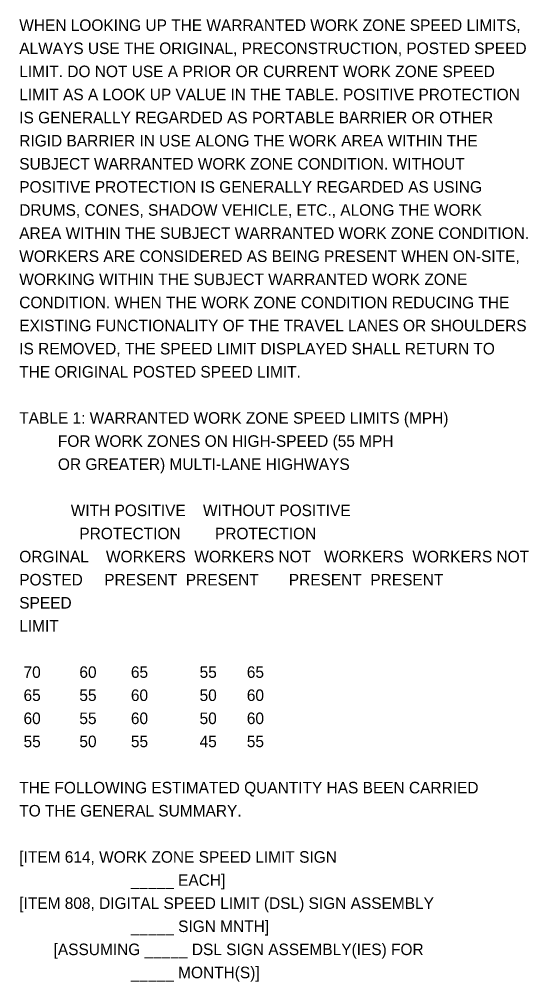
# Model space of a CAD drawing. Extents: x -9 to 65.1, y -15.6 to 23.2.
# Drawn here: x 39.08 to 45.25, y -8.1 to 3.56 of the extents above; entities that cross this region are included whole.
import ezdxf

# ---------------------------------------------------------------- set-up
doc = ezdxf.new("R2010")
doc.units = 0
doc.layers.add('SH_Text', color=7, linetype='Continuous')

msp = doc.modelspace()

# ---------------------------------------------------------------- texts
at = {"layer": 'SH_Text'}
for s, p in [('WHEN LOOKING UP THE WARRANTED WORK ZONE SPEED LIMITS,', (39.076, 3.42)), ('ALWAYS USE THE ORIGINAL, PRECONSTRUCTION, POSTED SPEED', (39.076, 3.14)), ('LIMIT. DO NOT USE A PRIOR OR CURRENT WORK ZONE SPEED', (39.076, 2.86)), ('LIMIT AS A LOOK UP VALUE IN THE TABLE. POSITIVE PROTECTION', (39.076, 2.58)), ('IS GENERALLY REGARDED AS PORTABLE BARRIER OR OTHER', (39.076, 2.3)), ('RIGID BARRIER IN USE ALONG THE WORK AREA WITHIN THE', (39.076, 2.02)), ('SUBJECT WARRANTED WORK ZONE CONDITION. WITHOUT', (39.076, 1.74)), ('POSITIVE PROTECTION IS GENERALLY REGARDED AS USING', (39.076, 1.46)), ('DRUMS, CONES, SHADOW VEHICLE, ETC., ALONG THE WORK', (39.076, 1.18)), ('AREA WITHIN THE SUBJECT WARRANTED WORK ZONE CONDITION.', (39.076, 0.9)), ('WORKERS ARE CONSIDERED AS BEING PRESENT WHEN ON-SITE,', (39.076, 0.62)), ('WORKING WITHIN THE SUBJECT WARRANTED WORK ZONE', (39.076, 0.34)), ('CONDITION. WHEN THE WORK ZONE CONDITION REDUCING THE', (39.076, 0.06)), ('EXISTING FUNCTIONALITY OF THE TRAVEL LANES OR SHOULDERS', (39.076, -0.22)), ('IS REMOVED, THE SPEED LIMIT DISPLAYED SHALL RETURN TO', (39.076, -0.5)), ('THE ORIGINAL POSTED SPEED LIMIT.', (39.076, -0.78)), ('TABLE 1: WARRANTED WORK ZONE SPEED LIMITS (MPH)', (39.076, -1.34)), ('         FOR WORK ZONES ON HIGH-SPEED (55 MPH', (39.076, -1.62)), ('         OR GREATER) MULTI-LANE HIGHWAYS', (39.076, -1.9)), ('            WITH POSITIVE    WITHOUT POSITIVE', (39.076, -2.46)), ('              PROTECTION        PROTECTION', (39.076, -2.74)), ('ORGINAL    WORKERS  WORKERS NOT   WORKERS  WORKERS NOT', (39.076, -3.02)), ('POSTED     PRESENT  PRESENT       PRESENT  PRESENT', (39.076, -3.3)), ('SPEED', (39.076, -3.58)), ('LIMIT', (39.076, -3.86)), (' 70         60        65            55       65', (39.076, -4.42)), (' 65         55        60            50       60', (39.076, -4.7)), (' 60         55        60            50       60', (39.076, -4.98)), (' 55         50        55            45       55', (39.076, -5.26)), ('THE FOLLOWING ESTIMATED QUANTITY HAS BEEN CARRIED', (39.076, -5.82)), ('TO THE GENERAL SUMMARY.', (39.076, -6.1)), ('[ITEM 614, WORK ZONE SPEED LIMIT SIGN', (39.076, -6.66)), ('                          _____ EACH]', (39.076, -6.94)), ('[ITEM 808, DIGITAL SPEED LIMIT (DSL) SIGN ASSEMBLY', (39.076, -7.22)), ('                          _____ SIGN MNTH]', (39.076, -7.5)), ('        [ASSUMING _____ DSL SIGN ASSEMBLY(IES) FOR', (39.076, -7.78)), ('                          _____ MONTH(S)]', (39.076, -8.06))]:
    msp.add_text(s, height=0.14, dxfattribs=at).set_placement(p)

doc.saveas('drawing.dxf')
